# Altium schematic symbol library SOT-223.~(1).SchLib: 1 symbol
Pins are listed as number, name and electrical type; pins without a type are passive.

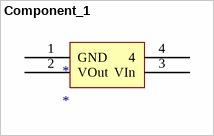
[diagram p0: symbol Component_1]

## Component_1
designator *
pins: 1 GND, 2 VOut, 3 VIn, 4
